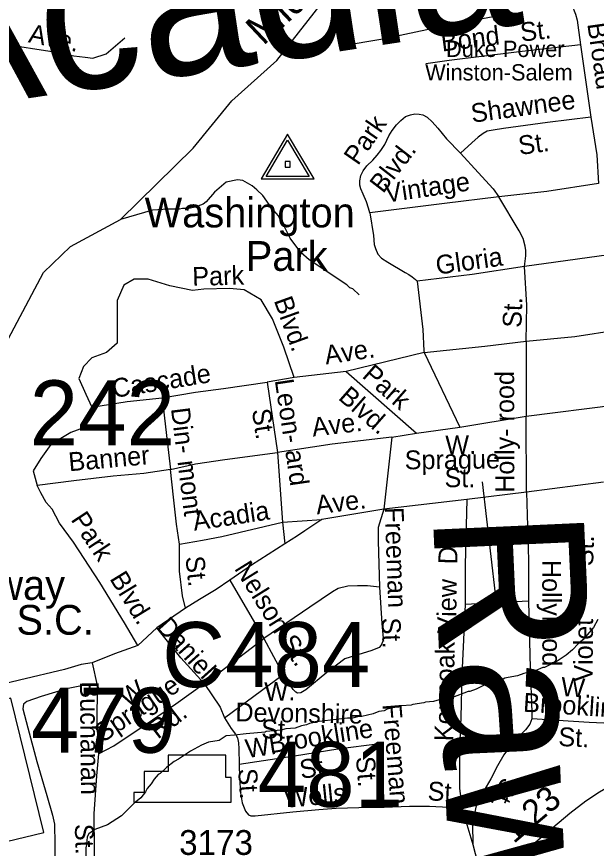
# Model space of a CAD drawing. Extents: x 1553981 to 1780076, y 812965 to 996873.
# Drawn here: x 1633164 to 1633529, y 846800 to 847325 of the extents above; entities that cross this region are included whole.
import ezdxf

# ---------------------------------------------------------------- set-up
doc = ezdxf.new("R2010")
doc.units = 0
for name, color, linetype in [('Exist Aviation Military CELL', 7, 'Continuous'), ('Exist Civil Demographics County Seat CELL', 7, 'Continuous'), ('Exist Cultural Hospital CELL', 7, 'Continuous'), ('Exist Cultural Shopping Center Building Footprint', 7, 'Continuous'), ('Exist Hydrographic Creek Single Shore', 7, 'Continuous'), ('Exist Hydrographic Creek Single Shore Label', 7, 'Continuous'), ('Exist Hydrographic Misc Water Feature', 7, 'Continuous'), ('Exist Road Non-System Type 51 Label', 7, 'Continuous'), ('Exist Road Secondary Mileage Hundredths English Label', 7, 'Continuous'), ('Exist Road Secondary Structure Culvert Number Label', 7, 'Continuous'), ('Exist Road Secondary Structure Standard Bridge Number Label', 7, 'Continuous'), ('Exist Road Secondary Type 51 Number Label', 7, 'Continuous'), ('Exist Road Secondary Type 51 Undivided 4 Lane Attributed', 7, 'Continuous'), ('Exist Utilities Electrical Transmission Line', 7, 'Continuous'), ('Map Preparation Border County Name Lower Right Label', 7, 'Continuous'), ('Map Preparation Logo CELL', 7, 'Continuous')]:
    doc.layers.add(name, color=color, linetype=linetype)

msp = doc.modelspace()

# ---------------------------------------------------------------- linework, layer by layer
at = {"layer": 'Exist Cultural Hospital CELL'}
for points in [[(1633351.12, 847222.31), (1633334.38, 847250.56), (1633317.69, 847222.31)], [(1633347.88, 847223.82), (1633320.94, 847223.82), (1633334.38, 847246.59)], [(1633335.91, 847229.65), (1633335.91, 847233.18), (1633332.88, 847233.18), (1633332.88, 847229.65)]]:
    msp.add_lwpolyline(points, close=True, dxfattribs=at)
at = {"layer": 'Exist Cultural Shopping Center Building Footprint'}
for points in [[(1633160, 846894.96), (1633032.18, 846863.81), (1633038.14, 846839.33), (1633142.54, 846864.78), (1633157.21, 846804.58), (1633180.64, 846810.29)], [(1633295.38, 846859.09), (1633259.06, 846859.09), (1633259.06, 846848.7), (1633243.96, 846848.7), (1633243.96, 846835.48), (1633237.36, 846835.48), (1633237.36, 846829.35), (1633298.68, 846829.35), (1633298.68, 846844.92), (1633295.38, 846844.92)]]:
    msp.add_lwpolyline(points, close=True, dxfattribs=at)
at = {"layer": 'Exist Hydrographic Creek Single Shore'}
for points in [[(1633299.11, 847271.57), (1633327.58, 847296.92), (1633394.31, 847382.36), (1633430.68, 847411.78), (1633453.91, 847425.16)], [(1632917.18, 846975.8), (1632932.11, 846987.72), (1632956.76, 847007.18), (1632979.41, 847017.37), (1632988.13, 847020.71), (1632995.6, 847023.75), (1633000.59, 847024.52), (1633004.53, 847024.38), (1633010, 847022.23), (1633015.33, 847022.72), (1633024.06, 847026.87), (1633038.32, 847035.31), (1633050.36, 847040.16), (1633070.89, 847047.68), (1633117.82, 847071.4), (1633145.21, 847097.1), (1633180.58, 847163.27), (1633197.46, 847179.75), (1633228.96, 847196.75), (1633274.9, 847241.63), (1633299.11, 847271.57)]]:
    msp.add_lwpolyline(points, dxfattribs=at)
at = {"layer": 'Exist Hydrographic Misc Water Feature'}
for points in [[(1633295.65, 847220.28), (1633288.28, 847213.92), (1633282.97, 847207.76), (1633281.2, 847206.4), (1633276.17, 847204.43), (1633272.16, 847203.57), (1633268.16, 847203.64), (1633266.15, 847203.16), (1633259.17, 847203.26), (1633249.16, 847202.65), (1633228.96, 847196.75)], [(1633379.52, 847149.16), (1633375.55, 847152.94), (1633373.56, 847153.7), (1633371.57, 847155.47), (1633347.95, 847171.15), (1633342.74, 847175.94), (1633336.06, 847184.98), (1633330.88, 847195.02), (1633329.4, 847197.02), (1633328.67, 847199.03), (1633324.21, 847204.07), (1633318.77, 847211.85), (1633315.04, 847215.38), (1633312.07, 847217.9), (1633306.1, 847221.19), (1633302.86, 847221.72), (1633295.65, 847220.28)], [(1633529.92, 846944.6), (1633527.14, 846939.62), (1633520.35, 846931.68), (1633517.33, 846929.21), (1633513.82, 846925.49), (1633509.79, 846922.02), (1633504.27, 846918.32), (1633496.24, 846914.39), (1633495.25, 846914.4), (1633490.23, 846912.19), (1633483.24, 846910.5), (1633479.23, 846909.03), (1633473.23, 846908.08), (1633471.23, 846907.59), (1633470.23, 846906.86), (1633464.22, 846905.65), (1633461.21, 846904.18), (1633460.22, 846904.18), (1633453.2, 846900.74), (1633449.19, 846899.28), (1633448.19, 846899.29), (1633438.18, 846895.37), (1633434.18, 846895.16), (1633426.17, 846892.97), (1633421.17, 846892.51), (1633420.17, 846892.02), (1633413.17, 846891.07), (1633412.16, 846890.58), (1633406.16, 846890.13), (1633397.17, 846887.95), (1633395.15, 846886.97), (1633391.91, 846886.5), (1633388.16, 846885.03), (1633381.15, 846883.34), (1633379.15, 846883.35), (1633375.15, 846882.38), (1633372.15, 846882.41), (1633354.16, 846880.31), (1633348.15, 846879.1), (1633346.15, 846878.12), (1633343.15, 846877.65), (1633339.14, 846876.18), (1633333.14, 846875.73), (1633330.14, 846874.75), (1633320.89, 846874.08), (1633320.14, 846873.59), (1633308.15, 846872.43), (1633300.89, 846871.63), (1633295.67, 846871.16), (1633291.22, 846868.25)], [(1633291.22, 846868.25), (1633284.55, 846867.24), (1633280.03, 846865.3), (1633273.24, 846861.65), (1633265.66, 846856.5), (1633262.9, 846855.04), (1633258.1, 846851.36), (1633254.05, 846847.42), (1633252.8, 846846.94), (1633250.26, 846843.97), (1633248.47, 846841), (1633245.93, 846838.04), (1633244.9, 846836.05), (1633241.85, 846832.09), (1633237.55, 846828.65), (1633229.7, 846820.77), (1633220.87, 846815.14), (1633212.84, 846812.25), (1633209.06, 846809.55), (1633208.03, 846807.57), (1633207.71, 846802.57), (1633207.19, 846800.58), (1633207.11, 846794.58)]]:
    msp.add_lwpolyline(points, dxfattribs=at)
at = {"layer": 'Exist Road Secondary Type 51 Undivided 4 Lane Attributed'}
msp.add_lwpolyline([(1633345.21, 846775.46), (1633393.64, 846774.51), (1633411.49, 846773.74), (1633422.41, 846773.74), (1633429.34, 846773.74), (1633437.34, 846775.29), (1633450.66, 846778.91), (1633458.65, 846782.01), (1633465.85, 846785.37), (1633478.9, 846794.42), (1633493.56, 846806.83), (1633512.21, 846822.6), (1633522.34, 846830.36), (1633530.86, 846836.05), (1633539.92, 846841.22), (1633550.31, 846845.87), (1633557.35, 846848.59)], dxfattribs=at)
at = {"layer": 'Exist Utilities Electrical Transmission Line'}
for points in [[(1633368.04, 847306.15), (1633394.34, 847310.57), (1633435.92, 847319.28), (1633463.96, 847324.67)], [(1633475.74, 847326.78), (1633475.95, 847323.77), (1633464.44, 847322.16), (1633463.96, 847324.67)]]:
    msp.add_lwpolyline(points, dxfattribs=at)
at = {"layer": 'Map Preparation Border County Name Lower Right Label'}
for p, q in [((1633536.68, 847174.35), (1633483.66, 847167.05)), ((1633484.72, 847119.91), (1633484.66, 847072.75)), ((1633420.37, 847112.92), (1633371.22, 847100.93)), ((1633420.37, 847112.92), (1633442.9, 847065.83)), ((1633371.22, 847100.93), (1633338.43, 847097.19)), ((1633371.22, 847100.93), (1633415.61, 847061.98)), ((1633338.43, 847097.19), (1633321.41, 847094.19)), ((1633321.41, 847094.19), (1633327.96, 847049.86)), ((1633484.66, 847072.75), (1633548.27, 847080.8)), ((1633442.9, 847065.83), (1633484.66, 847072.75)), ((1633484.84, 847024.8), (1633484.66, 847072.75)), ((1633400.07, 847059.47), (1633415.61, 847061.98)), ((1633415.61, 847061.98), (1633442.9, 847065.83)), ((1633400.07, 847059.47), (1633395.05, 847014.11)), ((1633327.96, 847049.86), (1633331.18, 847005.89)), ((1633533.44, 847031.06), (1633484.84, 847024.8)), ((1633447.31, 847020.15), (1633395.05, 847014.11)), ((1633484.84, 847024.8), (1633447.31, 847020.15)), ((1633395.05, 847014.11), (1633355.84, 847007.67)), ((1633331.18, 847005.89), (1633355.84, 847007.67)), ((1633331.18, 847005.89), (1633332.61, 846992.3)), ((1633297.95, 846969.41), (1633319.39, 846932.58)), ((1633486.18, 846956.18), (1633446.15, 846954.04)), ((1633269.91, 846951.62), (1633251.85, 846939.3)), ((1633251.85, 846939.3), (1633239.94, 846928.16)), ((1633319.39, 846932.58), (1633331.47, 846909.88)), ((1633211.16, 846917.31), (1633214.34, 846903.06)), ((1633294.63, 846882.64), (1633331.47, 846909.88))]:
    msp.add_line(p, q, dxfattribs=at)
for points in [[(1633493.5, 847408.13), (1633491.59, 847399.05), (1633493.02, 847386.62), (1633494.45, 847383.27), (1633495.94, 847379.45), (1633497.38, 847374.91), (1633499.54, 847368.14), (1633505.78, 847351.31), (1633513.46, 847331.94), (1633515.74, 847326.04), (1633516.82, 847322.37), (1633517.28, 847319.13), (1633518.83, 847306.84)], [(1633088.85, 847316.33), (1633104.08, 847314.51), (1633129.25, 847310.9), (1633157.45, 847306.88), (1633184.52, 847302.78), (1633199.72, 847299.84), (1633206.74, 847299.04), (1633211.58, 847298.37), (1633219.92, 847301.19), (1633231.8, 847311.26)], [(1633518.83, 847306.84), (1633478.54, 847302.21), (1633436.21, 847296.87), (1633421.44, 847294.84)], [(1633518.83, 847306.84), (1633522.45, 847281.81), (1633525.38, 847261.26)], [(1633386.21, 847200.88), (1633385.32, 847203.9), (1633384.13, 847207.9), (1633381.95, 847212.7), (1633380.51, 847215.95), (1633379.78, 847218.22), (1633379.84, 847220.97), (1633380.39, 847224.46), (1633381.92, 847227.43), (1633384.23, 847230.41), (1633388.04, 847234.08), (1633390.83, 847237.3), (1633393.11, 847240.26), (1633395.69, 847243.98), (1633398.23, 847249.34), (1633400.17, 847252.87), (1633402.87, 847256.37), (1633405.65, 847259.07), (1633408.7, 847261.53), (1633411.7, 847262.74), (1633414.47, 847263.19), (1633417.22, 847263.16), (1633419.46, 847262.61), (1633422.18, 847261.08), (1633425.4, 847258.26), (1633429.07, 847254.21), (1633434.46, 847247.62), (1633443.33, 847238.49)], [(1633525.38, 847261.26), (1633498.1, 847257.91), (1633470.31, 847254.1), (1633463.78, 847252.93), (1633460.02, 847252.26), (1633457.51, 847250.78), (1633454.46, 847248.59), (1633450.41, 847244.9), (1633443.33, 847238.49)], [(1633525.38, 847261.26), (1633529.28, 847237.44), (1633530.31, 847219.36)], [(1633443.33, 847238.49), (1633454.39, 847226.33), (1633463.96, 847215.93), (1633467.44, 847210.9)], [(1633530.31, 847219.36), (1633497.72, 847214.4), (1633467.44, 847210.9)], [(1633467.44, 847210.9), (1633433.17, 847206.67), (1633386.21, 847200.88)], [(1633483.66, 847167.05), (1633484.35, 847173.71), (1633484.35, 847177.05), (1633484.13, 847179.95), (1633482.73, 847184.66), (1633480.3, 847189.44), (1633467.44, 847210.9)], [(1633386.21, 847200.88), (1633388.55, 847186.6), (1633388.95, 847180.84), (1633389.68, 847178.32), (1633391.13, 847174.79), (1633393.58, 847172.26), (1633397.53, 847169.71), (1633408.43, 847163.28), (1633410.83, 847162.07), (1633412.84, 847160.49), (1633414.85, 847158.77), (1633416, 847157.83)], [(1633483.66, 847167.05), (1633450.71, 847162.08), (1633416, 847157.83)], [(1633484.72, 847119.91), (1633485.07, 847142.59), (1633483.66, 847167.05)], [(1633338.43, 847097.19), (1633332.01, 847116.28), (1633324.81, 847134.08), (1633317.62, 847145.94), (1633307.03, 847152.3), (1633297.72, 847153.15), (1633281.63, 847152.72), (1633274.43, 847151.88), (1633260.04, 847154.84), (1633246.49, 847159.08), (1633237.6, 847159.08), (1633231.25, 847155.27), (1633227.01, 847145.52), (1633227.01, 847129.84), (1633227.01, 847118.83), (1633220.24, 847112.89), (1633210.92, 847109.5), (1633205.84, 847104), (1633202.88, 847096.37), (1633207.11, 847086.62), (1633211.02, 847078.48)], [(1633416, 847157.83), (1633419.64, 847127.36), (1633420.25, 847113.98), (1633420.37, 847112.92)], [(1633484.72, 847119.91), (1633515.43, 847122.95), (1633542.35, 847127.21)], [(1633420.37, 847112.92), (1633458.65, 847116.93), (1633484.72, 847119.91)], [(1633255.31, 847084.33), (1633276.34, 847087.76), (1633294.04, 847090.12), (1633321.41, 847094.19)], [(1633211.02, 847078.48), (1633233.3, 847081.9), (1633255.31, 847084.33)], [(1633255.31, 847084.33), (1633257.96, 847060.54), (1633260.62, 847039.02)], [(1633211.02, 847078.48), (1633205.84, 847065.44), (1633197.8, 847062.47), (1633185.1, 847054.85), (1633178.75, 847045.95), (1633174.09, 847038.32), (1633176.63, 847029)], [(1633400.07, 847059.47), (1633362.51, 847055.06), (1633327.96, 847049.86)], [(1633260.62, 847039.02), (1633276.32, 847042.76), (1633294.87, 847045.32), (1633327.96, 847049.86)], [(1633260.62, 847039.02), (1633243.84, 847036.54), (1633224.34, 847034.81), (1633199.57, 847031.93), (1633176.63, 847029)], [(1633266.14, 846991.96), (1633264.33, 847004.73), (1633262.55, 847021.75), (1633260.62, 847039.02)], [(1633456.87, 847031.27), (1633465.09, 846960.83)], [(1633239.94, 846928.16), (1633231.67, 846942.53), (1633216.08, 846967.99), (1633199.48, 846993.21), (1633190.6, 847005.27), (1633185.94, 847014.17), (1633182.13, 847018.41), (1633178.75, 847024.34), (1633176.63, 847029)], [(1633447.31, 847020.15), (1633446.15, 846979.07), (1633446.15, 846954.04)], [(1633484.84, 847024.8), (1633486.18, 846981.93), (1633486.18, 846956.18)], [(1633395.05, 847014.11), (1633391.44, 847002.62), (1633391.31, 846994.11), (1633392.35, 846964.85)], [(1633266.14, 846991.96), (1633280.65, 846994.49), (1633292.84, 846996.89), (1633331.18, 847005.89)], [(1633355.84, 847007.67), (1633345.12, 847000.52), (1633340.48, 846997.3), (1633332.61, 846992.3)], [(1633269.91, 846951.62), (1633268.14, 846959.48), (1633266.13, 846974.98), (1633266.14, 846991.96)], [(1633332.61, 846992.3), (1633311.53, 846978.71), (1633297.95, 846969.41)], [(1633297.95, 846969.41), (1633289.28, 846963.4), (1633278.81, 846957.12), (1633269.91, 846951.62)], [(1633392.35, 846964.85), (1633384.79, 846965.84), (1633378.36, 846965.84), (1633372.28, 846965.48), (1633366.21, 846964.05), (1633362.63, 846961.9), (1633348.34, 846952.25), (1633319.39, 846932.58)], [(1633392.35, 846964.85), (1633393.76, 846942.09), (1633394.6, 846932.84), (1633394.33, 846930.84), (1633393.28, 846928.36), (1633392.02, 846926.86), (1633387.48, 846924.95), (1633370.4, 846919.85), (1633359.04, 846911.12), (1633345.89, 846900.34), (1633342.6, 846898.4), (1633340.59, 846898.17), (1633339.6, 846898.69), (1633337.88, 846900.47), (1633331.47, 846909.88)], [(1633446.15, 846954.04), (1633444.11, 846909.62), (1633443.4, 846882.8), (1633442.68, 846863.49), (1633442.68, 846853.48), (1633442.68, 846843.11), (1633442.68, 846838.11), (1633443.4, 846831.67), (1633444.11, 846825.95)], [(1633486.18, 846956.18), (1633487.25, 846913.99), (1633488.32, 846886.14), (1633488.26, 846881.89)], [(1633281.78, 846904.29), (1633267.05, 846920.5), (1633251.85, 846939.3)], [(1633281.78, 846904.29), (1633291.79, 846911.67), (1633319.39, 846932.58)], [(1633239.94, 846928.16), (1633225.18, 846922.95), (1633211.16, 846917.31)], [(1633211.16, 846917.31), (1633204.23, 846916.15), (1633193.68, 846913.11), (1633165.5, 846906.32), (1633124.24, 846896.48), (1633091.17, 846888.97), (1633057.26, 846881.26), (1633028.94, 846874.93), (1633010.52, 846868.8), (1633004.16, 846866.63), (1632990.09, 846862.77), (1632982.33, 846861.38), (1632973.4, 846859.6), (1632963.65, 846856.35), (1632952.79, 846853.17), (1632945.23, 846848.02), (1632937.96, 846841.06), (1632933.08, 846835.52), (1632930.03, 846826.36)], [(1633214.34, 846903.06), (1633205.61, 846902.94), (1633195.08, 846900.85), (1633179.03, 846896.1), (1633169.99, 846892.98), (1633167.95, 846891.27), (1633167.41, 846888.28), (1633170.72, 846876.23), (1633176.4, 846855.15), (1633182.56, 846833.59), (1633186.12, 846821.29), (1633187.53, 846815.53), (1633187.6, 846803.02), (1633187.64, 846791.18)], [(1633214.34, 846903.06), (1633214.23, 846879.33), (1633215.19, 846859.82)], [(1633215.19, 846859.82), (1633224.75, 846864.93), (1633245.19, 846878.62), (1633263.85, 846891.33), (1633281.78, 846904.29)], [(1633281.78, 846904.29), (1633291.77, 846889.34), (1633294.63, 846882.64)], [(1633294.63, 846882.64), (1633298.76, 846875.83), (1633301.47, 846872.27), (1633302.67, 846870.02), (1633303.38, 846866.76), (1633303.58, 846863), (1633303.91, 846853.49)], [(1633488.26, 846881.89), (1633487, 846878.51), (1633484.14, 846874.94), (1633476.99, 846867.79), (1633470.56, 846859.2), (1633466.63, 846852.41), (1633462.34, 846844.18), (1633458.05, 846836.67), (1633453.05, 846826.3), (1633450.9, 846815.58), (1633451.06, 846802.72)], [(1633556.92, 846878.09), (1633524.46, 846879.57), (1633488.26, 846881.89)], [(1633303.91, 846853.49), (1633338.74, 846858.71), (1633366.04, 846863.03), (1633392.32, 846866.37), (1633394, 846845.6), (1633395.21, 846826.34)], [(1633215.19, 846859.82), (1633213.83, 846846.04), (1633212.35, 846822.16), (1633212.5, 846798.67), (1633212.64, 846726.72)], [(1633303.91, 846853.49), (1633304.03, 846844.51), (1633304.64, 846835.24), (1633305.79, 846828.96), (1633307.71, 846823.7), (1633309.66, 846821.4), (1633311.16, 846820.9), (1633313.91, 846820.84), (1633337.69, 846823.24), (1633353.96, 846824.73), (1633364.95, 846825.56), (1633379.22, 846826.09), (1633395.21, 846826.34)], [(1633395.21, 846826.34), (1633411.2, 846826.85), (1633423.71, 846826.89), (1633444.11, 846825.95)], [(1633444.11, 846825.95), (1633446.61, 846817.37), (1633451.06, 846802.72)], [(1633451.06, 846802.72), (1633455.31, 846786.65), (1633455.81, 846785.01)]]:
    msp.add_lwpolyline(points, dxfattribs=at)

# ---------------------------------------------------------------- texts
at = {"layer": 'Exist Aviation Military CELL'}
for s, p in [('Parkway', (1633097.98, 846956.95)), ('Plaza S.C.', (1633093.8, 846934.98))]:
    msp.add_text(s, height=18.75, dxfattribs=at).set_placement(p)
at = {"layer": 'Exist Civil Demographics County Seat CELL'}
for s, p in [('Washington', (1633244.25, 847191.7)), ('Park', (1633308.01, 847164.31))]:
    msp.add_text(s, height=18.75, dxfattribs=at).set_placement(p)
at = {"layer": 'Exist Hydrographic Creek Single Shore Label'}
msp.add_text('Middle', height=18.75, rotation=43.2963, dxfattribs=at).set_placement((1633319.05, 847305.78))
at = {"layer": 'Exist Road Non-System Type 51 Label'}
for s, height, rotation, p in [('Acadia', 95, 8.5694, (1633099.61, 847262.31)), ('Ave.', 11.875, 348.7973, (1633170.54, 847308.44)), ('Bond', 11.875, 7.1941, (1633431.72, 847302.5)), ('St.', 11.875, 6.5619, (1633481.59, 847308.75)), ('Broad', 11.875, 278.2243, (1633523.15, 847319.97)), ('Shawnee', 11.875, 7.8115, (1633450.68, 847257.62)), ('Park', 11.875, 55.3199, (1633378.69, 847230.23)), ('St.', 11.875, 7.8115, (1633480.53, 847237.31)), ('Blvd.', 11.875, 52.2723, (1633394.49, 847212.58)), ('Vintage', 11.875, 8.3375, (1633396.53, 847207.26)), ('Gloria', 11.875, 7.9298, (1633428.52, 847161.87)), ('Park', 11.875, 1.483, (1633274.4, 847154.83)), ('Blvd.', 11.875, 289.8146, (1633325.54, 847145.65)), ('St.', 11.875, 87.7447, (1633481.61, 847128.27)), ('Ave.', 11.875, 8.3633, (1633358.49, 847105.27)), ('Cascade', 11.875, 9.2515, (1633224.81, 847084.14)), ('Park', 11.875, 318.7321, (1633380.71, 847097.51)), ('Holly- rood', 11.875, 90.0906, (1633477.19, 847024.39)), ('Leon- ard', 11.875, 278.409, (1633326.23, 847095.36)), ('Blvd.', 11.875, 318.7321, (1633365.69, 847083.75)), ('Din- mont', 11.875, 277.0614, (1633260.81, 847077.53)), ('St.', 11.875, 278.5481, (1633311.78, 847076.65)), ('Ave.', 11.875, 6.7038, (1633350.3, 847059.82)), ('W.', 11.875, 0.6462, (1633433.79, 847048.63)), ('Banner', 11.875, 5.0729, (1633196.75, 847037.96)), ('Sprague', 11.875, 0.5762, (1633408.16, 847039.2)), ('St.', 11.875, 0.1318, (1633433.23, 847027.93)), ('Ave.', 11.875, 7.1831, (1633352.83, 847010.8)), ('Acadia', 11.875, 8.5694, (1633275.51, 847000.5)), ('Park', 11.875, 303.3432, (1633197.41, 847007.56)), ('Freeman', 11.875, 272.0187, (1633395.54, 847015.2)), ('Rawson', 95, 272.6052, (1633425.78, 847011.59)), ('Dr.', 11.875, 88.7662, (1633441.17, 846979.23)), ('St.', 11.875, 87.7447, (1633526.77, 846978.08)), ('St.', 11.875, 275.9725, (1633269.96, 846984.04)), ('Nelson', 11.875, 301.8675, (1633300.45, 846976.71)), ('Hollyrood', 11.875, 270.0906, (1633494.79, 846982.16)), ('Blvd.', 11.875, 301.4889, (1633221.87, 846970.31)), ('View', 11.875, 89.0963, (1633440.47, 846935.56)), ('Daniel', 11.875, 311.98, (1633251.13, 846939.5)), ('St.', 11.875, 272.0187, (1633393.56, 846945.59)), ('Violet', 11.875, 89.5846, (1633526.51, 846905.29)), ('St.', 11.875, 304.7707, (1633329.03, 846929.89)), ('Konnoak', 11.875, 89.1303, (1633438.68, 846867.77)), ('Sprague', 11.875, 34.2364, (1633217.86, 846866.67)), ('W.', 11.875, 33.8201, (1633233.31, 846888.93)), ('W.', 11.875, 1.3596, (1633319.84, 846893.16)), ('W.', 11.875, 356.3464, (1633506.33, 846896.43)), ('Buchanan', 11.875, 270.5536, (1633203.49, 846905.52)), ('Brookline', 11.875, 356.3464, (1633482.5, 846886.51)), ('Rd.', 11.875, 37.7888, (1633252.61, 846868.76)), ('Devonshire', 11.875, 358.9423, (1633301.34, 846880.39)), ('Freeman', 11.875, 274.6215, (1633394.13, 846891.05)), ('St.', 11.875, 359.4524, (1633317.68, 846869.67)), ('Brookline', 11.875, 8.9981, (1633323.43, 846860.17)), ('St.', 11.875, 357.3808, (1633504.76, 846864.88)), ('W.', 11.875, 8.5259, (1633308.73, 846857.15)), ('St.', 11.875, 274.6215, (1633377.4, 846857.86)), ('St.', 11.875, 8.9981, (1633342.88, 846844.04)), ('St.', 11.875, 273.7799, (1633303.17, 846850.39)), ('St.', 11.875, 357.5444, (1633422.4, 846830.58)), ('St.', 11.875, 244.1184, (1633469.86, 846845.83)), ('Wells', 11.875, 5.7458, (1633333, 846825.75)), ('St.', 11.875, 271.6579, (1633200.23, 846815.64))]:
    msp.add_text(s, height=height, rotation=rotation, dxfattribs=at).set_placement(p)
at = {"layer": 'Exist Road Secondary Mileage Hundredths English Label'}
msp.add_text('1.23', height=15.625, rotation=40.2175, dxfattribs=at).set_placement((1633476.84, 846802.93))
at = {"layer": 'Exist Road Secondary Structure Culvert Number Label'}
msp.add_text('C484', height=41.01, dxfattribs=at).set_placement((1633255.32, 846901.95))
at = {"layer": 'Exist Road Secondary Structure Standard Bridge Number Label'}
for s, p in [('242', (1633171.87, 847054.26)), ('479', (1633172.57, 846860.58)), ('481', (1633315.54, 846826.49))]:
    msp.add_text(s, height=41.01, dxfattribs=at).set_placement(p)
at = {"layer": 'Exist Road Secondary Type 51 Number Label'}
msp.add_text('3173', height=15.625, dxfattribs=at).set_placement((1633266.03, 846796.2))
at = {"layer": 'Map Preparation Logo CELL'}
for s, height, p in [('Duke Power', 10.253, (1633434.17, 847299.09)), ('Winston-Salem', 10.2526, (1633421.02, 847284.31))]:
    msp.add_text(s, height=height, dxfattribs=at).set_placement(p)

doc.saveas('drawing.dxf')
